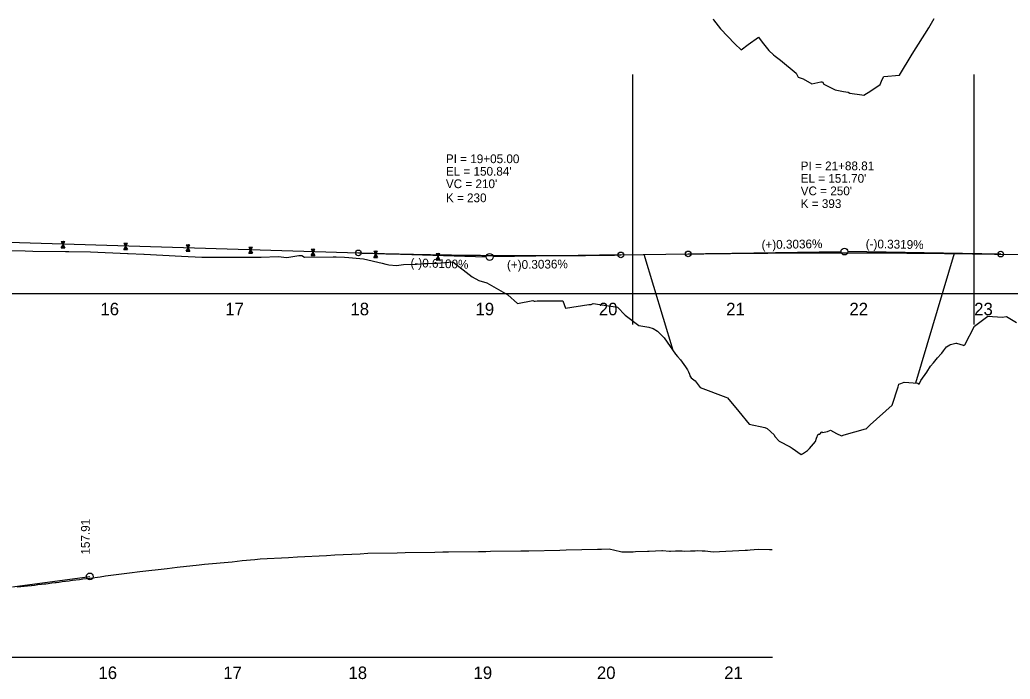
# Model space of a CAD drawing. Extents: x 573468 to 580768, y -57414 to -51768.
# Drawn here: x 574299 to 575092, y -54000 to -53472 of the extents above; entities that cross this region are included whole.
import ezdxf

# ---------------------------------------------------------------- set-up
doc = ezdxf.new("R2010")
doc.units = 0
for name, color, linetype in [('Exist Profile Cell', 7, 'Continuous'), ('Exist Vertical Profile Ground Line', 7, 'Continuous'), ('Exist Vertical Profile Horizontal Axis Label Major', 7, 'Continuous'), ('Old_Level_1', 7, 'Continuous'), ('Pattern 2', 7, 'Continuous'), ('Prop Vertical Profile Curve Label', 7, 'Continuous'), ('Prop Vertical Profile Grade', 7, 'Continuous'), ('Prop Vertical Profile Grade Label', 7, 'Continuous'), ('Prop VPI Label', 7, 'Continuous')]:
    doc.layers.add(name, color=color, linetype=linetype)

msp = doc.modelspace()

# ---------------------------------------------------------------- linework, layer by layer
at = {"layer": 'Exist Profile Cell'}
for p, q in [((574789.72, -53716.24), (574789.72, -53516.24)), ((575062.48, -53516.24), (575062.48, -53716.24)), ((573531.99, -53691.24), (576075.95, -53691.24)), ((573768.56, -53982.27), (574901.26, -53982.27))]:
    msp.add_line(p, q, dxfattribs=at)
at = {"layer": 'Exist Vertical Profile Ground Line'}
for points in [[(574853.82, -53471.6), (574854.19, -53472.41), (574859.75, -53479.59), (574871.24, -53491.57), (574876.45, -53496.32), (574881.81, -53492.09), (574890.22, -53486.15), (574893.02, -53490.33), (574898.42, -53496.92), (574902.26, -53500.5), (574903.62, -53501.58), (574907.7, -53504.77), (574920.22, -53514.93), (574920.54, -53515.46), (574922.04, -53518.37), (574925.94, -53519.71), (574932.8, -53523.61), (574940, -53521.93), (574940.51, -53521.89), (574941.39, -53521.93), (574942.39, -53523.82), (574945, -53525.23), (574951.58, -53528.48), (574958.27, -53529.76), (574961.99, -53530.38), (574963.2, -53530.93), (574972.95, -53532.36), (574974.32, -53532.62), (574980.13, -53529.16), (574987.43, -53524.11), (574989.03, -53520.02), (574990.46, -53517.68), (575003.02, -53516.75), (575013.16, -53499.72), (575026.4, -53478.77), (575030.72, -53471.35)], [(574290.51, -53656.97), (574303.67, -53657.3), (574309.79, -53657.44), (574335.81, -53657.76), (574338.51, -53657.82), (574355.88, -53658.01), (574385.55, -53659.34), (574386.05, -53659.36), (574398.52, -53659.93), (574398.88, -53659.94), (574428.55, -53661.42), (574444.97, -53662.24), (574445.66, -53662.28), (574470.78, -53662.37), (574475.84, -53662.2), (574483.18, -53662.18), (574492.26, -53662.23), (574505.86, -53661.69), (574512.97, -53662.64), (574522.52, -53661.03), (574524.91, -53660.94), (574527, -53662.35), (574550.06, -53661.97), (574552.36, -53661.88), (574558.98, -53662.39), (574562.64, -53662.63), (574574.14, -53663.53), (574589.04, -53667.1), (574592.22, -53667.79), (574593.42, -53668.13), (574594.45, -53668.36), (574600.68, -53668.84), (574606.34, -53668.24), (574616.66, -53667.8), (574622.84, -53667.32), (574624.78, -53667.45), (574632.77, -53666.98), (574645.7, -53665.99), (574661.24, -53677.89), (574666.48, -53681.04), (574673.02, -53682.89), (574689.64, -53692.42), (574697.41, -53699.43), (574709.6, -53697.06), (574710.67, -53697.37), (574711.64, -53697.44), (574713.27, -53697.11), (574733.57, -53697.16), (574735.76, -53703.14), (574754.43, -53700.04), (574756.4, -53700.16), (574757.96, -53699.39), (574777.51, -53702.19), (574783.66, -53708.7), (574794.49, -53716.83), (574799.3, -53717.66), (574802.44, -53718.32), (574805.85, -53719.35), (574809.5, -53721.59), (574814.62, -53726.82), (574823.86, -53739.82)], [(574823.86, -53739.82), (574825.43, -53741.61), (574827.67, -53744.45), (574831.81, -53749.92), (574833.43, -53752.43), (574834.21, -53754.13), (574834.9, -53755.93), (574835.37, -53757.1), (574836.23, -53758.72), (574839.42, -53761.32), (574843.41, -53766.49), (574863.94, -53774.19), (574865.34, -53774.83), (574874.39, -53785.68), (574882.7, -53795.77), (574895.19, -53798.46), (574897.09, -53799.47), (574902.61, -53804.46), (574903.31, -53805.64), (574906.69, -53809.49), (574915.45, -53814.02), (574917, -53814.94), (574924.42, -53820.03), (574925.47, -53819.64), (574929.44, -53816.84), (574931.05, -53815.47), (574935.7, -53809.85), (574936.63, -53806.94), (574937.88, -53803.91), (574939.32, -53803.81), (574940.85, -53802.03), (574941.3, -53802.6), (574945.35, -53801.74), (574947.76, -53800.8), (574952.71, -53803.37), (574956.62, -53805.09), (574958.75, -53804.33), (574975.78, -53799.72), (574976.11, -53799.88), (574979.41, -53796.46), (574997.17, -53780.61), (575001.8, -53765.9), (575002.54, -53763.91), (575003.96, -53763.27), (575006.72, -53762.36), (575017.72, -53763.15), (575018.68, -53763.9), (575020.12, -53761.06), (575024.82, -53754.18), (575027.83, -53749.56), (575030.29, -53746.93), (575033.28, -53742.85), (575036.26, -53739.52), (575036.75, -53738.97), (575038.29, -53737.25), (575040.44, -53734.12), (575043.28, -53732.49), (575043.71, -53732.17), (575047.92, -53731.14), (575048.68, -53731.04), (575053.82, -53732.72), (575054.19, -53733.04), (575055.23, -53732.29), (575063.07, -53717.54), (575073.5, -53709.43), (575085.04, -53710.39), (575088.61, -53709.64), (575096.46, -53714.47)], [(574297.25, -53926.12), (574300.16, -53925.8), (574302.78, -53925.51), (574305.54, -53925.2), (574308.31, -53924.9), (574308.72, -53924.86), (574311.07, -53924.57), (574313.84, -53924.25), (574316.6, -53923.92), (574319.37, -53923.6), (574320.09, -53923.51), (574322.13, -53923.25), (574324.9, -53922.9), (574327.67, -53922.55), (574328.47, -53922.45), (574330.43, -53922.2), (574333.2, -53921.85), (574335.96, -53921.51), (574338.73, -53921.16), (574339.91, -53921.01), (574341.49, -53920.79), (574344.26, -53920.39), (574347.02, -53920.03), (574349.79, -53919.68), (574352.55, -53919.32), (574355.32, -53918.97), (574363.53, -53917.92), (574367.75, -53917.33), (574386.99, -53914.88), (574395.33, -53913.81), (574417.1, -53911.38), (574425.27, -53910.33), (574442.86, -53908.37), (574447.08, -53907.83), (574469.31, -53905.95), (574477.07, -53905.06), (574487.39, -53904.19), (574491.48, -53903.71), (574514.21, -53902.54), (574521.45, -53902.12), (574544.52, -53900.93), (574551.42, -53900.52), (574571.46, -53899.49), (574577.65, -53899.13), (574601.21, -53898.72), (574607.61, -53898.6), (574631.41, -53898.19), (574637.57, -53898.08), (574642.17, -53898), (574666.28, -53897.72), (574672.17, -53897.65), (574675.79, -53897.61), (574700.08, -53897.32), (574701.07, -53897.31), (574706.61, -53897.25), (574731.23, -53896.57), (574736.36, -53896.52), (574761.39, -53895.83), (574764.62, -53895.79), (574770.78, -53895.62), (574779.71, -53897.8), (574780.87, -53898.1), (574781.69, -53898.11), (574789.93, -53897.89), (574791.69, -53897.84), (574801.36, -53897.54), (574802.67, -53897.5), (574812.83, -53897.02), (574813.48, -53897.03), (574819.06, -53897.48), (574819.77, -53897.54), (574823.82, -53897.29), (574824.89, -53897.28), (574829.21, -53897.32), (574830.67, -53897.41), (574835.8, -53897.34), (574839.6, -53897.21), (574841.57, -53897.07), (574845.11, -53897.3), (574847.56, -53897.34), (574849.63, -53897.58), (574851.93, -53897.83), (574854.05, -53898.03), (574879.44, -53896.6), (574881.34, -53896.59), (574883.43, -53896.49), (574889.95, -53895.86)], [(574889.95, -53895.86), (574898.87, -53896.19), (574901.25, -53896.2)]]:
    msp.add_lwpolyline(points, dxfattribs=at)
at = {"layer": 'Old_Level_1'}
for p, q in [((574821.83, -53736.97), (574798.78, -53660.13)), ((575046.78, -53659.24), (575015.65, -53763))]:
    msp.add_line(p, q, dxfattribs=at)
at = {"layer": 'Pattern 2'}
for p, q in [((574332.47, -53649.79), (574335.4, -53649.79)), ((574332.47, -53649.79), (574333.94, -53652.29)), ((574332.47, -53654.79), (574333.94, -53652.29)), ((574332.96, -53650.63), (574334.91, -53650.63)), ((574332.96, -53653.96), (574334.91, -53653.96)), ((574333.45, -53651.46), (574334.43, -53651.46)), ((574333.45, -53653.13), (574334.43, -53653.13)), ((574333.94, -53652.29), (574335.4, -53649.79)), ((574333.94, -53652.29), (574335.4, -53654.79)), ((574382.47, -53651.19), (574385.4, -53651.19)), ((574382.47, -53651.19), (574383.94, -53653.69)), ((574382.47, -53656.19), (574383.94, -53653.69)), ((574382.96, -53652.03), (574384.91, -53652.03)), ((574383.45, -53652.86), (574384.43, -53652.86)), ((574383.45, -53654.53), (574384.43, -53654.53)), ((574383.94, -53653.69), (574385.4, -53651.19)), ((574383.94, -53653.69), (574385.4, -53656.19)), ((574432.47, -53652.44), (574435.4, -53652.44)), ((574432.47, -53652.44), (574433.94, -53654.94)), ((574432.96, -53653.28), (574434.91, -53653.28)), ((574433.45, -53654.11), (574434.43, -53654.11)), ((574433.94, -53654.94), (574435.4, -53652.44)), ((574482.47, -53654.14), (574485.4, -53654.14)), ((574482.47, -53654.14), (574483.94, -53656.64)), ((574483.94, -53656.64), (574485.4, -53654.14)), ((574332.47, -53654.79), (574335.4, -53654.79)), ((574382.47, -53656.19), (574385.4, -53656.19)), ((574382.96, -53655.36), (574384.91, -53655.36)), ((574432.47, -53657.44), (574433.94, -53654.94)), ((574432.47, -53657.44), (574435.4, -53657.44)), ((574432.96, -53656.61), (574434.91, -53656.61)), ((574433.45, -53655.78), (574434.43, -53655.78)), ((574433.94, -53654.94), (574435.4, -53657.44)), ((574482.47, -53659.14), (574483.94, -53656.64)), ((574482.47, -53659.14), (574485.4, -53659.14)), ((574482.96, -53654.98), (574484.91, -53654.98)), ((574482.96, -53658.31), (574484.91, -53658.31)), ((574483.45, -53655.81), (574484.43, -53655.81)), ((574483.45, -53657.48), (574484.43, -53657.48)), ((574483.94, -53656.64), (574485.4, -53659.14)), ((574532.47, -53655.84), (574535.4, -53655.84)), ((574532.47, -53655.84), (574533.94, -53658.34)), ((574532.47, -53660.84), (574533.94, -53658.34)), ((574532.47, -53660.84), (574535.4, -53660.84)), ((574532.96, -53656.68), (574534.91, -53656.68)), ((574532.96, -53660.01), (574534.91, -53660.01)), ((574533.45, -53657.51), (574534.43, -53657.51)), ((574533.45, -53659.18), (574534.43, -53659.18)), ((574533.94, -53658.34), (574535.4, -53655.84)), ((574533.94, -53658.34), (574535.4, -53660.84)), ((574582.47, -53657.49), (574585.4, -53657.49)), ((574582.47, -53657.49), (574583.94, -53659.99)), ((574582.47, -53662.49), (574583.94, -53659.99)), ((574582.47, -53662.49), (574585.4, -53662.49)), ((574582.96, -53658.33), (574584.91, -53658.33)), ((574582.96, -53661.66), (574584.91, -53661.66)), ((574583.45, -53659.16), (574584.43, -53659.16)), ((574583.45, -53660.83), (574584.43, -53660.83)), ((574583.94, -53659.99), (574585.4, -53657.49)), ((574583.94, -53659.99), (574585.4, -53662.49)), ((574632.47, -53659.34), (574635.4, -53659.34)), ((574632.47, -53659.34), (574633.94, -53661.84)), ((574632.47, -53664.34), (574633.94, -53661.84)), ((574632.96, -53660.18), (574634.91, -53660.18)), ((574633.45, -53661.01), (574634.43, -53661.01)), ((574633.94, -53661.84), (574635.4, -53659.34)), ((574633.94, -53661.84), (574635.4, -53664.34)), ((574632.47, -53664.34), (574635.4, -53664.34)), ((574632.96, -53663.51), (574634.91, -53663.51)), ((574633.45, -53662.68), (574634.43, -53662.68))]:
    msp.add_line(p, q, dxfattribs=at)
at = {"layer": 'Prop Vertical Profile Curve Label'}
for centre in [(574570.13, -53658.85), (574780.13, -53660.46), (574833.94, -53659.64), (575083.94, -53659.82)]:
    msp.add_circle(centre, 2.25, dxfattribs=at)
at = {"layer": 'Prop Vertical Profile Grade'}
for p, q in [((573769.94, -53634.44), (574570.13, -53658.85)), ((574780.13, -53660.46), (574833.94, -53659.64)), ((575083.94, -53659.82), (575375.13, -53664.65)), ((574293.56, -53926.04), (574355.31, -53917.72))]:
    msp.add_line(p, q, dxfattribs=at)
for points in [[(574570.13, -53658.85), (574574.33, -53658.98), (574578.53, -53659.1), (574582.73, -53659.22), (574586.93, -53659.33), (574591.13, -53659.44), (574595.33, -53659.55), (574599.53, -53659.65), (574603.73, -53659.75), (574607.93, -53659.85), (574612.13, -53659.94), (574616.33, -53660.03), (574620.53, -53660.11), (574624.73, -53660.19), (574628.93, -53660.27), (574633.13, -53660.34), (574637.33, -53660.41), (574641.53, -53660.47), (574645.73, -53660.53), (574649.93, -53660.59), (574654.13, -53660.64), (574658.33, -53660.69), (574662.53, -53660.74), (574666.73, -53660.78), (574670.93, -53660.82), (574675.13, -53660.85), (574679.33, -53660.88), (574683.53, -53660.91), (574687.73, -53660.93), (574691.93, -53660.95), (574696.13, -53660.97), (574700.33, -53660.98), (574704.53, -53660.98), (574708.73, -53660.99), (574712.93, -53660.99), (574717.13, -53660.98), (574721.33, -53660.97), (574725.53, -53660.96), (574729.73, -53660.95), (574733.93, -53660.93), (574738.13, -53660.9), (574742.33, -53660.88), (574746.53, -53660.85), (574750.73, -53660.81), (574754.93, -53660.77), (574759.13, -53660.73), (574763.33, -53660.68), (574767.53, -53660.63), (574771.73, -53660.58), (574775.93, -53660.52), (574780.13, -53660.46)], [(574833.94, -53659.64), (574838.94, -53659.57), (574843.94, -53659.5), (574848.94, -53659.43), (574853.94, -53659.36), (574858.94, -53659.3), (574863.94, -53659.24), (574868.94, -53659.19), (574873.94, -53659.14), (574878.94, -53659.09), (574883.94, -53659.04), (574888.94, -53659), (574893.94, -53658.96), (574898.94, -53658.92), (574903.94, -53658.89), (574908.94, -53658.86), (574913.94, -53658.83), (574918.94, -53658.81), (574923.94, -53658.79), (574928.94, -53658.77), (574933.94, -53658.76), (574938.94, -53658.75), (574943.94, -53658.74), (574948.94, -53658.74), (574953.94, -53658.73), (574958.94, -53658.74), (574963.94, -53658.74), (574968.94, -53658.75), (574973.94, -53658.76), (574978.94, -53658.78), (574983.94, -53658.79), (574988.94, -53658.82), (574993.94, -53658.84), (574998.94, -53658.87), (575003.94, -53658.9), (575008.94, -53658.93), (575013.94, -53658.97), (575018.94, -53659.01), (575023.94, -53659.05), (575028.94, -53659.1), (575033.94, -53659.15), (575038.94, -53659.2), (575043.94, -53659.26), (575048.94, -53659.32), (575053.94, -53659.38), (575058.94, -53659.44), (575063.94, -53659.51), (575068.94, -53659.58), (575073.94, -53659.66), (575078.94, -53659.74), (575083.94, -53659.82)]]:
    msp.add_spline(points, degree=3, dxfattribs=at)
at = {"layer": 'Prop VPI Label'}
for p, q in [((574570.13, -53658.85), (574672.38, -53661.97)), ((574780.13, -53660.46), (574677.88, -53662.01)), ((574833.94, -53659.64), (574956.19, -53657.79)), ((575083.94, -53659.82), (574961.69, -53657.79))]:
    msp.add_line(p, q, dxfattribs=at)
for centre in [(574675.13, -53662.05), (574958.94, -53657.74), (574355.31, -53917.72)]:
    msp.add_circle(centre, 2.75, dxfattribs=at)

# ---------------------------------------------------------------- texts
at = {"layer": 'Exist Vertical Profile Horizontal Axis Label Major'}
for s, p in [('16', (574363.81, -53708.74)), ('17', (574463.67, -53708.74)), ('18', (574563.8, -53708.74)), ('19', (574663.84, -53708.74)), ('20', (574762.52, -53708.74)), ('21', (574864.36, -53708.74)), ('22', (574962.91, -53708.74)), ('23', (575062.74, -53708.74)), ('16', (574362.25, -53999.77)), ('17', (574462.1, -53999.77)), ('18', (574562.23, -53999.77)), ('19', (574662.27, -53999.77)), ('20', (574760.95, -53999.77)), ('21', (574862.79, -53999.77))]:
    msp.add_text(s, height=10, dxfattribs=at).set_placement(p)
at = {"layer": 'Pattern 2'}
for s, p in [('6"', (574333.82, -53649.69)), ('6"', (574383.82, -53651.09)), ('6"', (574433.82, -53652.34)), ('6"', (574483.82, -53654.04)), ('-6"', (574333.36, -53655.4)), ('-6"', (574383.36, -53656.8)), ('-6"', (574433.36, -53658.05)), ('-6"', (574483.36, -53659.75)), ('-6"', (574533.36, -53661.45)), ('6"', (574533.82, -53655.74)), ('-6"', (574583.36, -53663.1)), ('6"', (574583.82, -53657.39)), ('6"', (574633.82, -53659.24)), ('-6"', (574633.36, -53664.95))]:
    msp.add_text(s, height=0.5, rotation=360, dxfattribs=at).set_placement(p)
at = {"layer": 'Prop Vertical Profile Curve Label'}
for s, p in [("VC = 210'", (574640.13, -53607.05)), ("VC = 250'", (574923.94, -53612.74)), ('K = 230', (574640.13, -53618.28)), ('K = 393', (574923.94, -53622.93))]:
    msp.add_text(s, height=7, dxfattribs=at).set_placement(p)
at = {"layer": 'Prop Vertical Profile Grade Label'}
for s, rotation, p in [('(+)0.3036%', 0.86963, (574892.69, -53655.75)), ('(-)0.3319%', 359.04926, (574975.9, -53655.02)), ('(-)0.6100%', 358.25304, (574611.77, -53670.12)), ('(+)0.3036%', 0.86963, (574689.06, -53671.84))]:
    msp.add_text(s, height=7, rotation=rotation, dxfattribs=at).set_placement(p)
at = {"layer": 'Prop VPI Label'}
for s, p in [('PI = 19+05.00', (574640.13, -53587.05)), ("EL = 150.84'", (574640.13, -53597.05)), ('PI = 21+88.81', (574923.94, -53592.74)), ("EL = 151.70'", (574923.94, -53602.74))]:
    msp.add_text(s, height=7, dxfattribs=at).set_placement(p)
msp.add_text('157.91', height=7, rotation=90, dxfattribs=at).set_placement((574355.31, -53900.22))

doc.saveas('drawing.dxf')
